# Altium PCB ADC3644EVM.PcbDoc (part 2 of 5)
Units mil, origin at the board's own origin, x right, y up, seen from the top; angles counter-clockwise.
Board outline 3900 x 2716.54 mil, 10 copper layers (Top Layer, L2 GND, L3 PWR, L4 GND, L5 SIG, L6 GND, L7 GND, L8 PWR, L9 GND, Bottom Layer), stack 61.2 mil thick; 368 components, 252 nets, 1539 pads, 1019 vias.
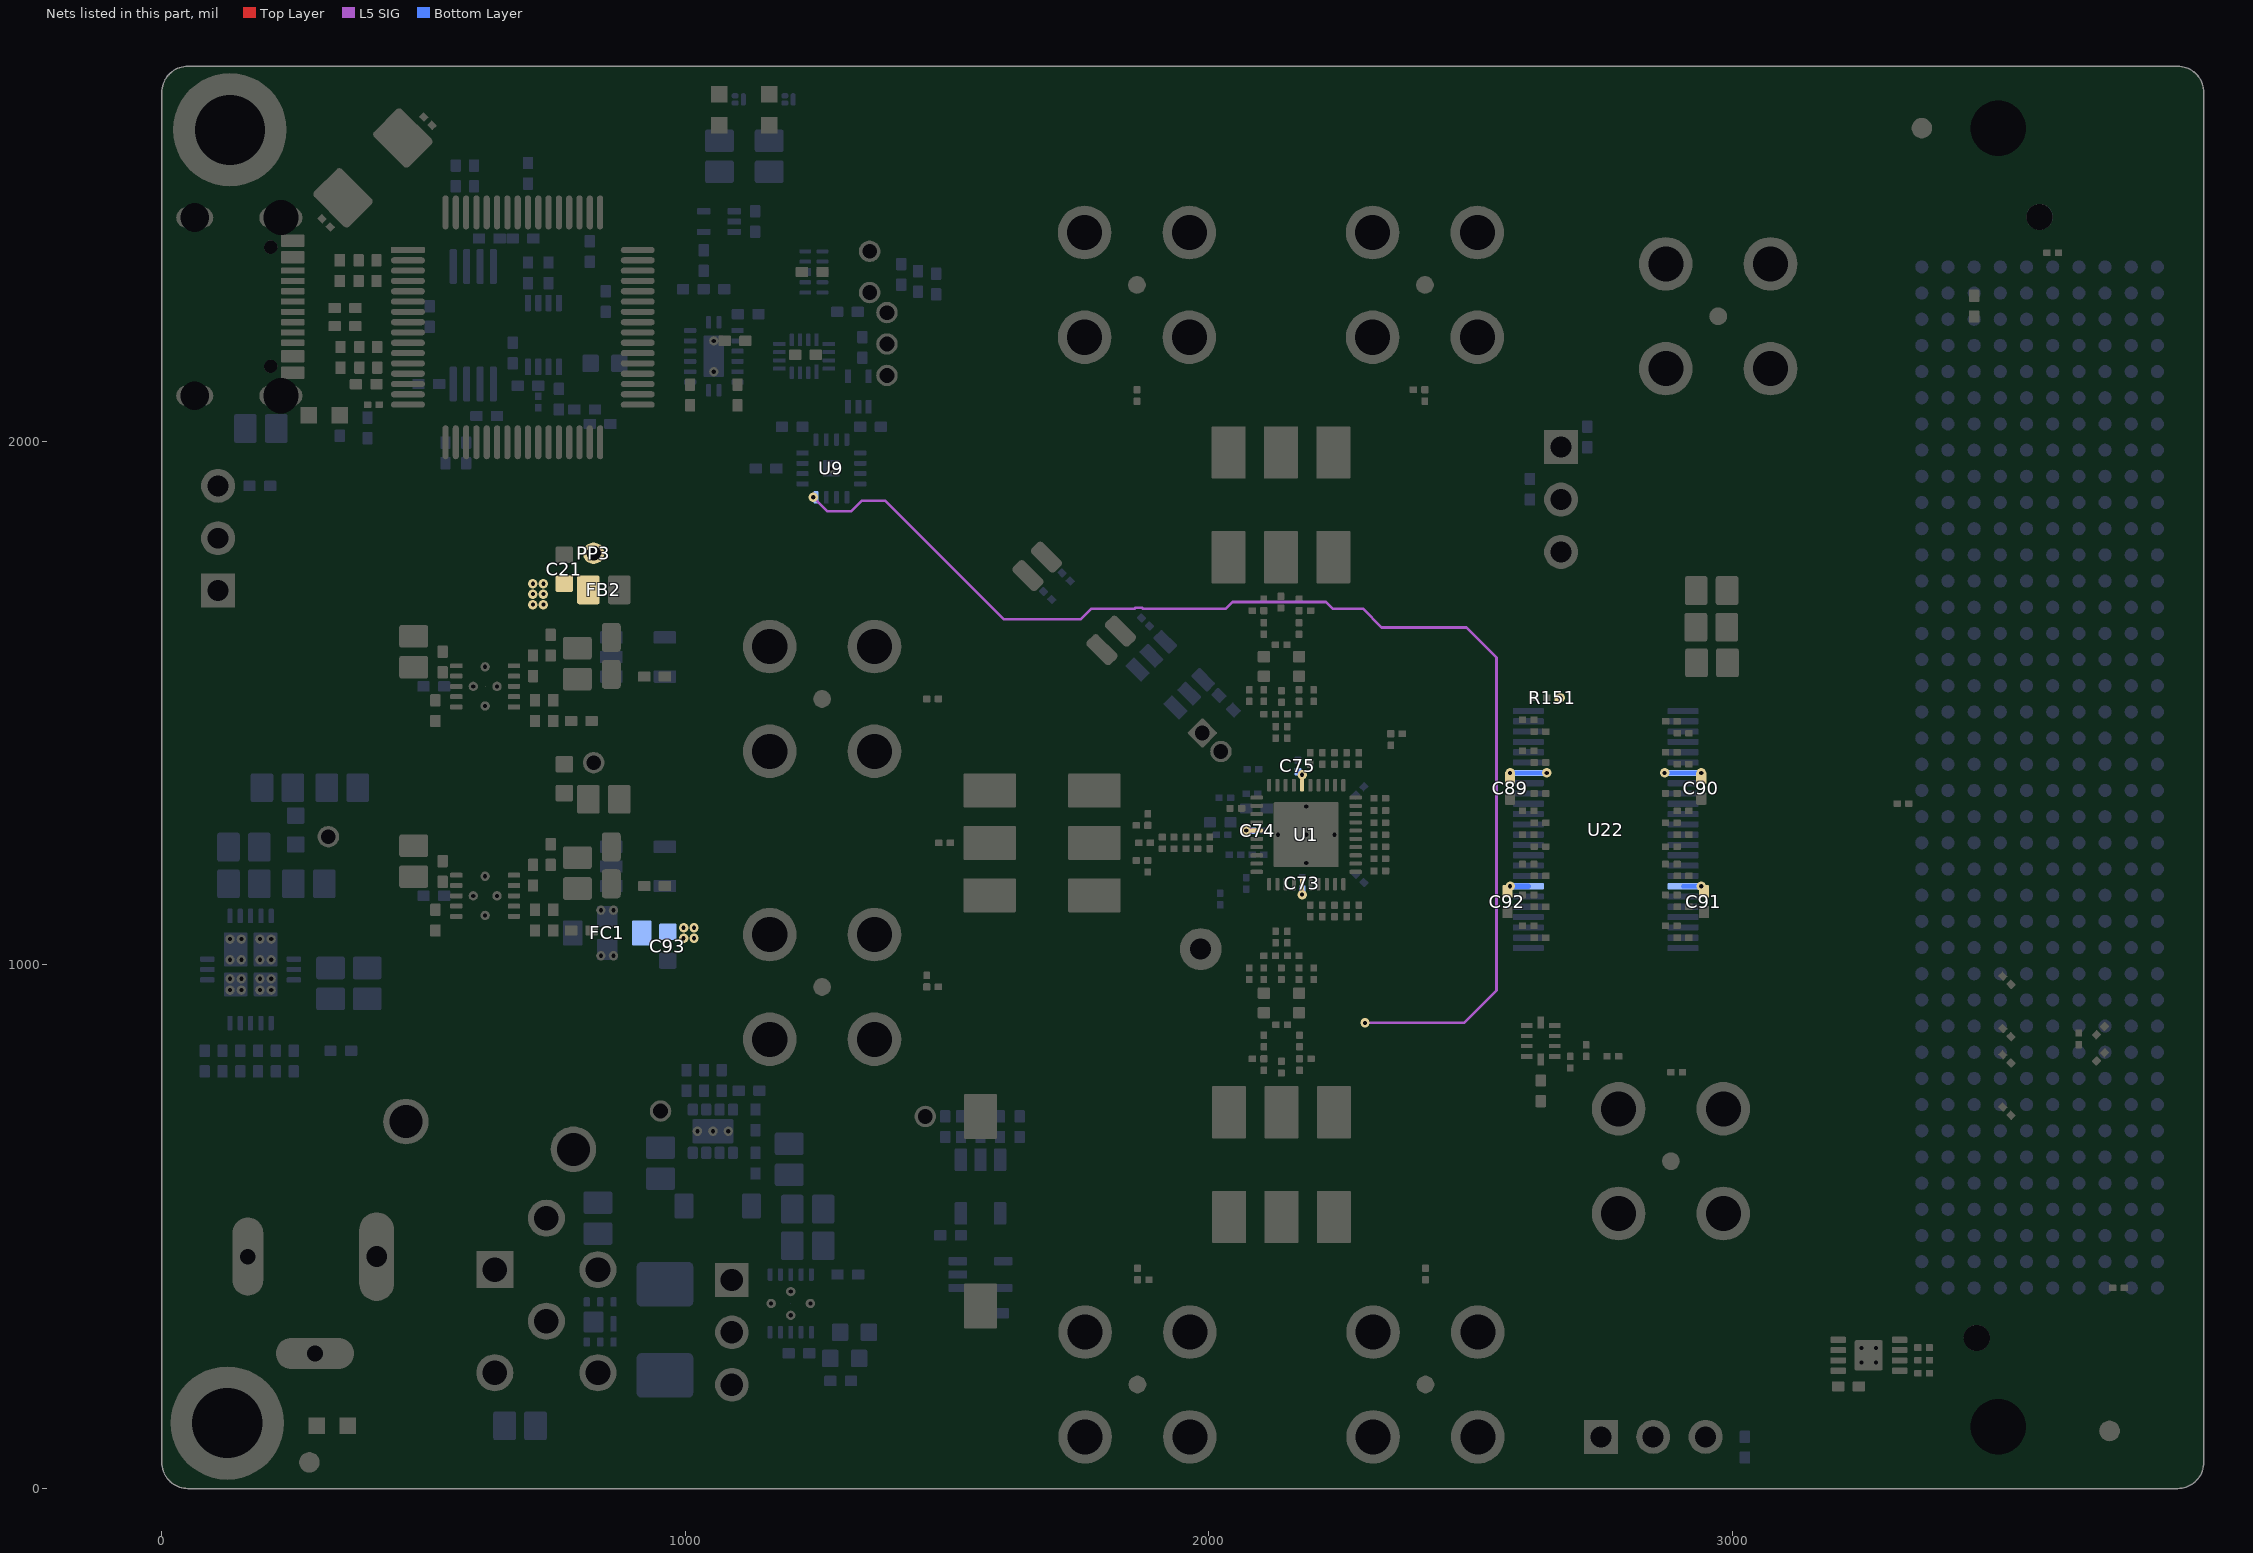
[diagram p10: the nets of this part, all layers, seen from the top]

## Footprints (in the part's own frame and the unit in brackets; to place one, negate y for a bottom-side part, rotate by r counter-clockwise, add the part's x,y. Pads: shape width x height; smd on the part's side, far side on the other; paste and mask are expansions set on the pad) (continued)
IND_LQG15H [mm] "MuRata"
  rrect20% 0.55x0.6 smd mask+0.07: 1(-0.475,0) 2(0.475,0)
  body extent -0.52,-0.27 0.52,0.27, height 0.55
Keystone5010 [mil] "Keystone Multipurpose loops"
  round 87 hole 63: 1(0,0)
  silkscreen extent -70,-70 70,70, body extent -63,-63 63,62, height 319
KEYSTONE5116 [mil] "For Keystone 500x miniature loop terminals"
  round 80 hole 40: 1(0,0)
  silkscreen extent -58,-58 58,58, body extent -50,-49 50,51, height 183
Keystone5125 [mil] "Keystone Multipurpose loops"
  round 87 hole 63: 1(0,0)
  silkscreen extent -70,-70 70,70, body extent -63,-63 63,62, height 319
Label_650x200 [mil] "Thermal Transfer Label"
  silkscreen extent -325,-100 325,100
LED_LTST-C190-Green [mm] "Lite-On"
  rect 0.8x0.8 smd: 1(-0.75,0) 2(0.75,0)
  silkscreen extent -1.1,-0.8 1.8,0.8, body extent -0.85,-0.45 0.85,0.45, height 0.91
LQFP64-MFG [mm]
  rrect33% 1.65x0.3 smd paste+0 mask+0.05: 1(-5.575,3.75)
  rrect100% 1.65x0.3 smd paste+0 mask+0.05: 2(-5.575,3.25) 3(-5.575,2.75) 4(-5.575,2.25) 5(-5.575,1.75) 6(-5.575,1.25) 7(-5.575,0.75) 8(-5.575,0.25) 9(-5.575,-0.25) 10(-5.575,-0.75) 11(-5.575,-1.25) 12(-5.575,-1.75) 13(-5.575,-2.25) 14(-5.575,-2.75) 15(-5.575,-3.25) 16(-5.575,-3.75) 33(5.575,-3.75) 34(5.575,-3.25) 35(5.575,-2.75) 36(5.575,-2.25) 37(5.575,-1.75) 38(5.575,-1.25) 39(5.575,-0.75) 40(5.575,-0.25) 41(5.575,0.25) 42(5.575,0.75) 43(5.575,1.25) 44(5.575,1.75) 45(5.575,2.25) 46(5.575,2.75) 47(5.575,3.25) 48(5.575,3.75)
  rrect100% 0.3x1.65 smd paste+0 mask+0.05: 17(-3.75,-5.575) 18(-3.25,-5.575) 19(-2.75,-5.575) 20(-2.25,-5.575) 21(-1.75,-5.575) 22(-1.25,-5.575) 23(-0.75,-5.575) 24(-0.25,-5.575) 25(0.25,-5.575) 26(0.75,-5.575) 27(1.25,-5.575) 28(1.75,-5.575) 29(2.25,-5.575) 30(2.75,-5.575) 31(3.25,-5.575) 32(3.75,-5.575) 49(3.75,5.575) 50(3.25,5.575) 51(2.75,5.575) 52(2.25,5.575) 53(1.75,5.575) 54(1.25,5.575) 55(0.75,5.575) 56(0.25,5.575) 57(-0.25,5.575) 58(-0.75,5.575) 59(-1.25,5.575) 60(-1.75,5.575) 61(-2.25,5.575) 62(-2.75,5.575) 63(-3.25,5.575) 64(-3.75,5.575)
  silkscreen extent -7.12,-5.05 5.05,5.05, body extent -6.5,-6.5 6.5,6.5, height 0.25
NFM31PC [mm]
  rrect10% 0.95x1.2 smd paste+0: 1(-1.675,0) 3(1.675,0)
  round 0.2 / inner round 0.454 / far side round 0.454 hole 0.2 mask+0.05: 2(-0.305,-1.105) 2(-0.305,1.105) 2(0.305,-1.105) 2(0.305,1.105)
  rrect10% 1x1 smd paste+0: 2(0,-0.8) 2(0,0.8)
  body extent -1.7,-0.9 1.7,0.9, height 1.5
PBC03SAAN [mm] "Sullins 100mil, 1x3, 230 mil above insulator"
  rect 1.65x1.65 hole 1.016: 1(-2.54,0)
  round 1.65 hole 1.016: 2(0,0) 3(2.54,0)
  silkscreen extent -3.81,-1.27 3.81,1.6, body extent -3.81,-1.27 3.81,1.27, height 8.38
ProbePoint_TH_40mil [mil]
  round 41 hole 28: 1(0,0)
RAPC722X [mm] "Conn_DC Jack"
  oval 1.7x4.3 hole 1.01 slot 3.56 at 90 deg: 1(14.194,0)
  oval 1.5x3.8 hole 0.76 slot 3.05 at 90 deg: 2(7.946,0)
  oval 3.8x1.5 hole 0.76 slot 3.05 at 0 deg: 3(11.197,-4.7)
  silkscreen extent 0.2,-4.57 14.93,4.57, body extent 0.58,-4.97 15.06,4.56, height 10.92
RDU0028A [mm]
  round 0.025 smd mask+0.05: 1(-1.987,2.487) 2(-2.1,1.25) 6(-2.1,-1.25) 7(-1.987,-2.488) 13(1.987,-2.488) 14(2.1,-1.25) 18(2.1,1.25) 19(1.988,2.488)
  rrect40% 0.7x0.25 smd paste+0 mask+0.05: 3(-2.1,0.5) 4(-2.1,0) 5(-2.1,-0.5) 15(2.1,-0.5) 16(2.1,0) 17(2.1,0.5)
  rrect40% 0.25x0.7 smd paste+0 mask+0.05: 8(-1,-2.6) 9(-0.5,-2.6) 10(0,-2.6) 11(0.5,-2.6) 12(1,-2.6) 20(1,2.6) 21(0.5,2.6) 22(0,2.6) 23(-0.5,2.6) 24(-1,2.6)
  round 0.454 hole 0.2 mask+0.102: 25(-1,1) 25(-1,0.45) 25(-0.45,1) 25(-0.45,0.45) 26(-1,-1.475) 26(-1,-0.475) 26(-0.45,-1.475) 26(-0.45,-0.475) 27(0.45,-1.475) 27(0.45,-0.475) 27(1,-1.475) 27(1,-0.475) 28(0.45,1) 28(0.45,0.45) 28(1,1) 28(1,0.45)
  rrect9% 1.15x1.15 smd paste-1000 mask+0.05: 25(-0.725,0.725) 28(0.725,0.725)
  rrect9% 1.15x1.65 smd paste-1000 mask+0.05: 26(-0.725,-0.975) 27(0.725,-0.975)
  Top Layer region: -2.4,1.625 -1.8,1.625 -1.781,1.621 -1.765,1.61 -1.754,1.594 -1.75,1.575 -1.75,1.575 -1.75,0.925 -1.754,0.906 -1.765,0.89 -1.781,0.879 -1.8,0.875 -1.8,0.875 -2.4,0.875 -2.419,0.879 -2.435,0.89 -2.446,0.906 -2.45,0.925 -2.45,0.925 -2.45,1.075 -2.443,1.1 -2.425,1.118 -2.4,1.125 -2.4,1.125 -2.225,1.125 -2.187,1.133 -2.154,1.154 -2.133,1.187 -2.125,1.225 -2.125,1.225 -2.125,1.275 -2.138,1.325 -2.175,1.362 -2.225,1.375 -2.225,1.375 -2.4,1.375 -2.419,1.379 -2.435,1.39 -2.446,1.406 -2.45,1.425 -2.45,1.425 -2.45,1.575 -2.443,1.6 -2.425,1.618 -2.4,1.625
  Top Layer region: -2.4,-0.875 -1.8,-0.875 -1.775,-0.882 -1.757,-0.9 -1.75,-0.925 -1.75,-0.925 -1.75,-1.575 -1.754,-1.594 -1.765,-1.61 -1.781,-1.621 -1.8,-1.625 -1.8,-1.625 -2.4,-1.625 -2.419,-1.621 -2.435,-1.61 -2.446,-1.594 -2.45,-1.575 -2.45,-1.575 -2.45,-1.425 -2.443,-1.4 -2.425,-1.382 -2.4,-1.375 -2.4,-1.375 -2.225,-1.375 -2.187,-1.367 -2.154,-1.346 -2.133,-1.313 -2.125,-1.275 -2.125,-1.275 -2.125,-1.225 -2.138,-1.175 -2.175,-1.138 -2.225,-1.125 -2.225,-1.125 -2.4,-1.125 -2.419,-1.121 -2.435,-1.11 -2.446,-1.094 -2.45,-1.075 -2.45,-1.075 -2.45,-0.925 -2.443,-0.9 -2.425,-0.882 -2.4,-0.875
  Top Layer region: -1.575,-2.95 -1.55,-2.943 -1.532,-2.925 -1.525,-2.9 -1.525,-2.9 -1.525,-2.075 -1.529,-2.056 -1.54,-2.04 -1.556,-2.029 -1.575,-2.025 -1.575,-2.025 -2.4,-2.025 -2.423,-2.033 -2.439,-2.051 -2.445,-2.075 -2.445,-2.075 -2.45,-2.225 -2.443,-2.25 -2.425,-2.268 -2.4,-2.275 -2.4,-2.275 -2.225,-2.275 -2.187,-2.283 -2.154,-2.304 -2.133,-2.337 -2.125,-2.375 -2.125,-2.375 -2.125,-2.575 -2.118,-2.6 -2.1,-2.618 -2.075,-2.625 -2.075,-2.625 -1.875,-2.625 -1.837,-2.633 -1.804,-2.654 -1.783,-2.687 -1.775,-2.725 -1.775,-2.725 -1.775,-2.9 -1.768,-2.925 -1.75,-2.943 -1.725,-2.95 -1.725,-2.95
  Top Layer region: 1.575,-2.95 1.55,-2.943 1.532,-2.925 1.525,-2.9 1.525,-2.9 1.525,-2.075 1.529,-2.056 1.54,-2.04 1.556,-2.029 1.575,-2.025 1.575,-2.025 2.4,-2.025 2.423,-2.033 2.439,-2.051 2.445,-2.075 2.445,-2.075 2.45,-2.225 2.443,-2.25 2.425,-2.268 2.4,-2.275 2.4,-2.275 2.225,-2.275 2.187,-2.283 2.154,-2.304 2.133,-2.337 2.125,-2.375 2.125,-2.375 2.125,-2.575 2.118,-2.6 2.1,-2.618 2.075,-2.625 2.075,-2.625 1.875,-2.625 1.837,-2.633 1.804,-2.654 1.783,-2.687 1.775,-2.725 1.775,-2.725 1.775,-2.9 1.768,-2.925 1.75,-2.943 1.725,-2.95 1.725,-2.95
  Top Layer region: 2.4,-1.625 1.8,-1.625 1.775,-1.618 1.757,-1.6 1.75,-1.575 1.75,-1.575 1.75,-0.925 1.754,-0.906 1.765,-0.89 1.781,-0.879 1.8,-0.875 1.8,-0.875 2.4,-0.875 2.419,-0.879 2.435,-0.89 2.446,-0.906 2.45,-0.925 2.45,-0.925 2.45,-1.075 2.443,-1.1 2.425,-1.118 2.4,-1.125 2.4,-1.125 2.225,-1.125 2.187,-1.133 2.154,-1.154 2.133,-1.187 2.125,-1.225 2.125,-1.225 2.125,-1.275 2.138,-1.325 2.175,-1.362 2.225,-1.375 2.225,-1.375 2.4,-1.375 2.419,-1.379 2.435,-1.39 2.446,-1.406 2.45,-1.425 2.45,-1.425 2.45,-1.575 2.443,-1.6 2.425,-1.618 2.4,-1.625
  Top Layer region: 2.4,0.875 1.8,0.875 1.775,0.882 1.757,0.9 1.75,0.925 1.75,0.925 1.75,1.575 1.754,1.594 1.765,1.61 1.781,1.621 1.8,1.625 1.8,1.625 2.4,1.625 2.419,1.621 2.435,1.61 2.446,1.594 2.45,1.575 2.45,1.575 2.45,1.425 2.443,1.4 2.425,1.382 2.4,1.375 2.4,1.375 2.225,1.375 2.187,1.367 2.154,1.346 2.133,1.313 2.125,1.275 2.125,1.275 2.125,1.225 2.138,1.175 2.175,1.138 2.225,1.125 2.225,1.125 2.4,1.125 2.419,1.121 2.435,1.11 2.446,1.094 2.45,1.075 2.45,1.075 2.45,0.925 2.443,0.9 2.425,0.882 2.4,0.875
  Top Layer region: 1.575,2.95 1.55,2.943 1.532,2.925 1.525,2.9 1.525,2.9 1.525,2.075 1.529,2.056 1.54,2.04 1.556,2.029 1.575,2.025 1.575,2.025 2.4,2.025 2.423,2.033 2.439,2.051 2.445,2.075 2.445,2.075 2.45,2.225 2.443,2.25 2.425,2.268 2.4,2.275 2.4,2.275 2.225,2.275 2.187,2.283 2.154,2.304 2.133,2.337 2.125,2.375 2.125,2.375 2.125,2.575 2.118,2.6 2.1,2.618 2.075,2.625 2.075,2.625 1.875,2.625 1.837,2.633 1.804,2.654 1.783,2.687 1.775,2.725 1.775,2.725 1.775,2.9 1.768,2.925 1.75,2.943 1.725,2.95 1.725,2.95
  Top Layer region: -1.575,2.95 -1.55,2.943 -1.532,2.925 -1.525,2.9 -1.525,2.9 -1.525,2.075 -1.529,2.056 -1.54,2.04 -1.556,2.029 -1.575,2.025 -1.575,2.025 -2.4,2.025 -2.423,2.033 -2.439,2.051 -2.445,2.075 -2.445,2.075 -2.45,2.225 -2.443,2.25 -2.425,2.268 -2.4,2.275 -2.4,2.275 -2.225,2.275 -2.187,2.283 -2.154,2.304 -2.133,2.337 -2.125,2.375 -2.125,2.375 -2.125,2.575 -2.118,2.6 -2.1,2.618 -2.075,2.625 -2.075,2.625 -1.875,2.625 -1.837,2.633 -1.804,2.654 -1.783,2.687 -1.775,2.725 -1.775,2.725 -1.775,2.9 -1.768,2.925 -1.75,2.943 -1.725,2.95 -1.725,2.95
  silkscreen extent -3.2,-3.13 2.63,3.13, body extent -2.25,-2.75 2.25,2.75, height 1.9
RSB0040E [mm] "WQFN-40"
  rrect50% 0.6x0.2 smd mask+0.05: 1(-2.4,1.8) 2(-2.4,1.4) 3(-2.4,1) 4(-2.4,0.6) 5(-2.4,0.2) 6(-2.4,-0.2) 7(-2.4,-0.6) 8(-2.4,-1) 9(-2.4,-1.4) 10(-2.4,-1.8) 21(2.4,-1.8) 22(2.4,-1.4) 23(2.4,-1) 24(2.4,-0.6) 25(2.4,-0.2) 26(2.4,0.2) 27(2.4,0.6) 28(2.4,1) 29(2.4,1.4) 30(2.4,1.8)
  rrect50% 0.2x0.6 smd mask+0.05: 11(-1.8,-2.4) 12(-1.4,-2.4) 13(-1,-2.4) 14(-0.6,-2.4) 15(-0.2,-2.4) 16(0.2,-2.4) 17(0.6,-2.4) 18(1,-2.4) 19(1.4,-2.4) 20(1.8,-2.4) 31(1.8,2.4) 32(1.4,2.4) 33(1,2.4) 34(0.6,2.4) 35(0.2,2.4) 36(-0.2,2.4) 37(-0.6,2.4) 38(-1,2.4) 39(-1.4,2.4) 40(-1.8,2.4)
  round 0.2 / inner round 0.454 / far side round 0.454 hole 0.2 mask+0.05: 41(-1.37,0) 41(0,-1.37) 41(0,0) 41(0,1.37) 41(1.37,0)
  rrect3% 3.15x3.15 smd paste-1.75 mask+0.05: 41(0,0)
  silkscreen extent -2.86,2.27 -2.8,2.33, body extent -2.5,-2.5 2.5,2.5, height 0.8
RSE0010A [mm] "QFN, 10-Leads, Body 1.5x2mm, Pitch 0.5mm, TI Recommended"
  rrect20% 0.55x0.25 smd mask+0.07: 1(-0.675,0.75) 4(-0.675,-0.75) 6(0.675,-0.75) 9(0.675,0.75)
  rrect20% 0.55x0.2 smd mask+0.07: 2(-0.675,0.25) 3(-0.675,-0.25) 7(0.675,-0.25) 8(0.675,0.25)
  rrect20% 0.3x0.6 smd mask+0.07: 5(0,-0.9) 10(0,0.9)
  silkscreen extent -1.07,-1.17 0.77,1.18, body extent -0.75,-1 0.75,1, height 0.54
RSV0016A [mm] "QFN, 16-Leads, Body 1.8x2.6mm, Pitch 0.4mm, TI Recommended"
  rrect25% 0.7x0.2 smd mask+0.05: 1(-0.75,0.6)
  rrect25% 0.6x0.2 smd mask+0.05: 2(-0.8,0.2) 3(-0.8,-0.2) 4(-0.8,-0.6) 9(0.8,-0.6) 10(0.8,-0.2) 11(0.8,0.2) 12(0.8,0.6)
  rrect25% 0.2x0.6 smd mask+0.05: 5(-0.6,-1.2) 6(-0.2,-1.2) 7(0.2,-1.2) 8(0.6,-1.2) 13(0.6,1.2) 14(0.2,1.2) 15(-0.2,1.2) 16(-0.6,1.2)
  silkscreen extent -1.08,-1.33 1.08,1.45, body extent -0.85,-1.31 0.85,1.31, height 0.49
RTE0016D [mm]
  rrect42% 0.6x0.24 smd paste+0 mask+0.07: 1(-1.4,0.75) 2(-1.4,0.25) 3(-1.4,-0.25) 4(-1.4,-0.75) 9(1.4,-0.75) 10(1.4,-0.25) 11(1.4,0.25) 12(1.4,0.75)
  rrect42% 0.24x0.6 smd paste+0 mask+0.07: 5(-0.75,-1.4) 6(-0.25,-1.4) 7(0.25,-1.4) 8(0.75,-1.4) 13(0.75,1.4) 14(0.25,1.4) 15(-0.25,1.4) 16(-0.75,1.4)
  round 0.454 hole 0.2 mask+0.05: 17(0,0)
  rrect6% 0.8x0.8 smd paste-0.04 mask+0: 17(0,0)
  silkscreen extent -2.06,-1.55 1.55,1.55, body extent -1.5,-1.5 1.5,1.5, height 0.8
SAMTEC_ASP-134488-01 [mm]
  round 0.64 smd paste+0.125: A1(24.74,5.715) A2(23.47,5.715) A3(22.2,5.715) A4(20.93,5.715) A5(19.66,5.715) A6(18.39,5.715) A7(17.12,5.715) A8(15.85,5.715) A9(14.58,5.715) A10(13.31,5.715) A11(12.04,5.715) A12(10.77,5.715) A13(9.5,5.715) A14(8.23,5.715) A15(6.96,5.715) A16(5.69,5.715) A17(4.42,5.715) A18(3.15,5.715) A19(1.88,5.715) A20(0.61,5.715) A21(-0.66,5.715) A22(-1.93,5.715) A23(-3.2,5.715) A24(-4.47,5.715) A25(-5.74,5.715) A26(-7.01,5.715) A27(-8.28,5.715) A28(-9.55,5.715) A29(-10.82,5.715) A30(-12.09,5.715) A31(-13.36,5.715) A32(-14.63,5.715) A33(-15.9,5.715) A34(-17.17,5.715) A35(-18.44,5.715) A36(-19.71,5.715) A37(-20.98,5.715) A38(-22.25,5.715) A39(-23.52,5.715) A40(-24.79,5.715) B1(24.74,4.445) B2(23.47,4.445) B3(22.2,4.445) B4(20.93,4.445) B5(19.66,4.445) B6(18.39,4.445) B7(17.12,4.445) B8(15.85,4.445) B9(14.58,4.445) B10(13.31,4.445) B11(12.04,4.445) B12(10.77,4.445) B13(9.5,4.445) B14(8.23,4.445) B15(6.96,4.445) B16(5.69,4.445) B17(4.42,4.445) B18(3.15,4.445) B19(1.88,4.445) B20(0.61,4.445) B21(-0.66,4.445) B22(-1.93,4.445) B23(-3.2,4.445) B24(-4.47,4.445) B25(-5.74,4.445) B26(-7.01,4.445) B27(-8.28,4.445) B28(-9.55,4.445) B29(-10.82,4.445) B30(-12.09,4.445) B31(-13.36,4.445) B32(-14.63,4.445) B33(-15.9,4.445) B34(-17.17,4.445) B35(-18.44,4.445) B36(-19.71,4.445) B37(-20.98,4.445) B38(-22.25,4.445) B39(-23.52,4.445) B40(-24.79,4.445) C1(24.74,3.175) C2(23.47,3.175) C3(22.2,3.175) C4(20.93,3.175) C5(19.66,3.175) C6(18.39,3.175) C7(17.12,3.175) C8(15.85,3.175) C9(14.58,3.175) C10(13.31,3.175) C11(12.04,3.175) C12(10.77,3.175) C13(9.5,3.175) C14(8.23,3.175) C15(6.96,3.175) C16(5.69,3.175) C17(4.42,3.175) C18(3.15,3.175) C19(1.88,3.175) C20(0.61,3.175) C21(-0.66,3.175) C22(-1.93,3.175) C23(-3.2,3.175) C24(-4.47,3.175) C25(-5.74,3.175) C26(-7.01,3.175) C27(-8.28,3.175) C28(-9.55,3.175) C29(-10.82,3.175) C30(-12.09,3.175) C31(-13.36,3.175) C32(-14.63,3.175) C33(-15.9,3.175) C34(-17.17,3.175) C35(-18.44,3.175) C36(-19.71,3.175) C37(-20.98,3.175) C38(-22.25,3.175) C39(-23.52,3.175) C40(-24.79,3.175) D1(24.74,1.905) D2(23.47,1.905) D3(22.2,1.905) D4(20.93,1.905) D5(19.66,1.905) D6(18.39,1.905) D7(17.12,1.905) D8(15.85,1.905) D9(14.58,1.905) D10(13.31,1.905) D11(12.04,1.905) D12(10.77,1.905) D13(9.5,1.905) D14(8.23,1.905) D15(6.96,1.905) D16(5.69,1.905) D17(4.42,1.905) D18(3.15,1.905) D19(1.88,1.905) D20(0.61,1.905) D21(-0.66,1.905) D22(-1.93,1.905) D23(-3.2,1.905) D24(-4.47,1.905) D25(-5.74,1.905) D26(-7.01,1.905) D27(-8.28,1.905) D28(-9.55,1.905) D29(-10.82,1.905) D30(-12.09,1.905) D31(-13.36,1.905) D32(-14.63,1.905) D33(-15.9,1.905) D34(-17.17,1.905) D35(-18.44,1.905) D36(-19.71,1.905) D37(-20.98,1.905) D38(-22.25,1.905) D39(-23.52,1.905) D40(-24.79,1.905) E1(24.74,0.635) E2(23.47,0.635) E3(22.2,0.635) E4(20.93,0.635) E5(19.66,0.635) E6(18.39,0.635) E7(17.12,0.635) E8(15.85,0.635) E9(14.58,0.635) E10(13.31,0.635) E11(12.04,0.635) E12(10.77,0.635) E13(9.5,0.635) E14(8.23,0.635) E15(6.96,0.635) E16(5.69,0.635) E17(4.42,0.635) E18(3.15,0.635) E19(1.88,0.635) E20(0.61,0.635) E21(-0.66,0.635) E22(-1.93,0.635) E23(-3.2,0.635) E24(-4.47,0.635) E25(-5.74,0.635) E26(-7.01,0.635) E27(-8.28,0.635) E28(-9.55,0.635) E29(-10.82,0.635) E30(-12.09,0.635) E31(-13.36,0.635) E32(-14.63,0.635) E33(-15.9,0.635) E34(-17.17,0.635) E35(-18.44,0.635) E36(-19.71,0.635) E37(-20.98,0.635) E38(-22.25,0.635) E39(-23.52,0.635) E40(-24.79,0.635) F1(24.74,-0.635) F2(23.47,-0.635) F3(22.2,-0.635) F4(20.93,-0.635) F5(19.66,-0.635) F6(18.39,-0.635) F7(17.12,-0.635) F8(15.85,-0.635) F9(14.58,-0.635) F10(13.31,-0.635) F11(12.04,-0.635) F12(10.77,-0.635) F13(9.5,-0.635) F14(8.23,-0.635) F15(6.96,-0.635) F16(5.69,-0.635) F17(4.42,-0.635) F18(3.15,-0.635) F19(1.88,-0.635) F20(0.61,-0.635) F21(-0.66,-0.635) F22(-1.93,-0.635) F23(-3.2,-0.635) F24(-4.47,-0.635) F25(-5.74,-0.635) F26(-7.01,-0.635) F27(-8.28,-0.635) F28(-9.55,-0.635) F29(-10.82,-0.635) F30(-12.09,-0.635) F31(-13.36,-0.635) F32(-14.63,-0.635) F33(-15.9,-0.635) F34(-17.17,-0.635) F35(-18.44,-0.635) F36(-19.71,-0.635) F37(-20.98,-0.635) F38(-22.25,-0.635) F39(-23.52,-0.635) F40(-24.79,-0.635) G1(24.74,-1.905) G2(23.47,-1.905) G3(22.2,-1.905) G4(20.93,-1.905) G5(19.66,-1.905) G6(18.39,-1.905) G7(17.12,-1.905) G8(15.85,-1.905) G9(14.58,-1.905) G10(13.31,-1.905) G11(12.04,-1.905) G12(10.77,-1.905) G13(9.5,-1.905) G14(8.23,-1.905) G15(6.96,-1.905) G16(5.69,-1.905) G17(4.42,-1.905) G18(3.15,-1.905) G19(1.88,-1.905) G20(0.61,-1.905) G21(-0.66,-1.905) G22(-1.93,-1.905) G23(-3.2,-1.905) G24(-4.47,-1.905) G25(-5.74,-1.905) G26(-7.01,-1.905) G27(-8.28,-1.905) G28(-9.55,-1.905) G29(-10.82,-1.905) G30(-12.09,-1.905) G31(-13.36,-1.905) G32(-14.63,-1.905) G33(-15.9,-1.905) G34(-17.17,-1.905) G35(-18.44,-1.905) G36(-19.71,-1.905) G37(-20.98,-1.905) G38(-22.25,-1.905) G39(-23.52,-1.905) G40(-24.79,-1.905) H1(24.74,-3.175) H2(23.47,-3.175) H3(22.2,-3.175) H4(20.93,-3.175) H5(19.66,-3.175) H6(18.39,-3.175) H7(17.12,-3.175) H8(15.85,-3.175) H9(14.58,-3.175) H10(13.31,-3.175) H11(12.04,-3.175) H12(10.77,-3.175) H13(9.5,-3.175) H14(8.23,-3.175) H15(6.96,-3.175) H16(5.69,-3.175) H17(4.42,-3.175) H18(3.15,-3.175) H19(1.88,-3.175) H20(0.61,-3.175) H21(-0.66,-3.175) H22(-1.93,-3.175) H23(-3.2,-3.175) H24(-4.47,-3.175) H25(-5.74,-3.175) H26(-7.01,-3.175) H27(-8.28,-3.175) H28(-9.55,-3.175) H29(-10.82,-3.175) H30(-12.09,-3.175) H31(-13.36,-3.175) H32(-14.63,-3.175) H33(-15.9,-3.175) H34(-17.17,-3.175) H35(-18.44,-3.175) H36(-19.71,-3.175) H37(-20.98,-3.175) H38(-22.25,-3.175) H39(-23.52,-3.175) H40(-24.79,-3.175) J1(24.74,-4.445) J2(23.47,-4.445) J3(22.2,-4.445) J4(20.93,-4.445) J5(19.66,-4.445) J6(18.39,-4.445) J7(17.12,-4.445) J8(15.85,-4.445) J9(14.58,-4.445) J10(13.31,-4.445) J11(12.04,-4.445) J12(10.77,-4.445) J13(9.5,-4.445) J14(8.23,-4.445) J15(6.96,-4.445) J16(5.69,-4.445) J17(4.42,-4.445) J18(3.15,-4.445) J19(1.88,-4.445) J20(0.61,-4.445) J21(-0.66,-4.445) J22(-1.93,-4.445) J23(-3.2,-4.445) J24(-4.47,-4.445) J25(-5.74,-4.445) J26(-7.01,-4.445) J27(-8.28,-4.445) J28(-9.55,-4.445) J29(-10.82,-4.445) J30(-12.09,-4.445) J31(-13.36,-4.445) J32(-14.63,-4.445) J33(-15.9,-4.445) J34(-17.17,-4.445) J35(-18.44,-4.445) J36(-19.71,-4.445) J37(-20.98,-4.445) J38(-22.25,-4.445) J39(-23.52,-4.445) J40(-24.79,-4.445) K1(24.74,-5.715) K2(23.47,-5.715) K3(22.2,-5.715) K4(20.93,-5.715) K5(19.66,-5.715) K6(18.39,-5.715) K7(17.12,-5.715) K8(15.85,-5.715) K9(14.58,-5.715) K10(13.31,-5.715) K11(12.04,-5.715) K12(10.77,-5.715) K13(9.5,-5.715) K14(8.23,-5.715) K15(6.96,-5.715) K16(5.69,-5.715) K17(4.42,-5.715) K18(3.15,-5.715) K19(1.88,-5.715) K20(0.61,-5.715) K21(-0.66,-5.715) K22(-1.93,-5.715) K23(-3.2,-5.715) K24(-4.47,-5.715) K25(-5.74,-5.715) K26(-7.01,-5.715) K27(-8.28,-5.715) K28(-9.55,-5.715) K29(-10.82,-5.715) K30(-12.09,-5.715) K31(-13.36,-5.715) K32(-14.63,-5.715) K33(-15.9,-5.715) K34(-17.17,-5.715) K35(-18.44,-5.715) K36(-19.71,-5.715) K37(-20.98,-5.715) K38(-22.25,-5.715) K39(-23.52,-5.715) K40(-24.79,-5.715)
  round 0 hole 2.69 unplated: ""(-31.521,-2.007) ""(31.471,-2.007)
  round 1.27 hole 1.27 unplated: ""(-27.216,-3.05) ""(27.166,0)
  silkscreen extent -27.92,-7.34 28.75,7.76, body extent -27.91,-7.34 28.76,7.34, height 7.11
SIL0008D [mm] "SIP, 8-Leads, Body 2.8x3.0mm, Pitch 0.65mm, Thermal Pad 1.9x1.1mm"
  rrect12% 1.04x0.85 on Bottom Paste: 0(0,-0.525) 0(0,0.525)
  rrect40% 0.6x0.5 smd paste-0.05 mask-0.05: 1(-1.05,0.975) 2(-1.05,0.325) 3(-1.05,-0.325) 4(-1.05,-0.975) 5(1.05,-0.975) 6(1.05,-0.325) 7(1.05,0.325) 8(1.05,0.975)
  round 0.457 hole 0.203 mask+0.05: 9(0,-0.75) 9(0,0) 9(0,0.75)
  rrect17% 1.2x2 smd paste-0.6 mask-0.05: 9(0,0)
  silkscreen extent -1.53,-1.63 1.53,1.63, body extent -1.4,-1.5 1.4,1.5, height 1.53
SMBJ15CA [mil]
  rrect20% 85x107.99 smd: 1(-87.01,0) 2(87.01,0)
  silkscreen extent -125,-79 125,79, body extent -104,-73 104,73, height 89
SOD-123 [mm] "On Semi recommended land pattern"
  rrect20% 0.915x1.22 smd: 1(-1.637,0) 2(1.637,0)
  silkscreen extent -2.74,-1.17 2.03,1.17, body extent -1.93,-0.9 1.93,0.9, height 1.35
SPC02SYAN [mil] "SULLINS"
  round 1 on Mech3: 0(0,0)
  body extent -98,-47 99,47, height 366
TDFN8 [mm]
  rrect30% 0.75x0.3 smd paste+0 mask+0.05: 1(-1.5,0.75) 2(-1.5,0.25) 3(-1.5,-0.25) 4(-1.5,-0.75) 5(1.478,-0.75) 6(1.478,-0.25) 7(1.478,0.25) 8(1.478,0.75)
  round 0.327 / inner round 0.454 / far side round 0.454 hole 0.2 mask+0.05: 9(-0.354,0.354) 9(-0.354,-0.354) 9(0.354,0.354) 9(0.354,-0.354)
  rrect10% 1.36x1.46 smd paste+0 mask+0.05: 9(0,0)
  silkscreen extent -1.56,1.07 -1.4,1.22, body extent -1.5,-1 1.5,1, height 0.75
TI_Stacked_Overlay_Small_Vertical [mil]
  silkscreen extent -66,-288 69,288
TSSOP-8 [mm] "TSSOP, 8-Leads, Body 3.1x4.5mm (max), Pitch 0.65mm, IPC Medium Density"
  rrect50% 1.7x0.35 smd: 1(-2.85,0.975) 2(-2.85,0.325) 3(-2.85,-0.325) 4(-2.85,-0.975) 5(2.85,-0.975) 6(2.85,-0.325) 7(2.85,0.325) 8(2.85,0.975)
  silkscreen extent -2.97,-1.55 1.6,1.82, body extent -3.2,-1.55 3.2,1.55, height 1.07
WEEE_Minimum [mil] "WEEElie bin"
  silkscreen extent -95,-172 99,104
XTAL_ABM3 [mm] "Abracon recommended land pattern 12.28.10"
  rrect20% 1.9x2.4 smd: 1(-2.05,0) 2(2.05,0)
  silkscreen extent -2.67,-1.78 2.67,1.78, body extent -2.6,-1.7 2.6,1.7, height 1.3
YJM0003A [mm] "SMT, 3-Leads, Body 0.69x0.6mm"
  rrect80% 0.35x0.25 smd paste-0.2 mask-0.05: 1(-0.175,0.175) 2(-0.175,-0.175)
  rrect50% 0.25x0.2 on Bottom Paste: 1(-0.175,0.2) 2(-0.175,-0.2)
  rrect80% 0.25x0.6 smd paste-0.05 mask-0.05: 3(0.225,0)
  body extent -0.35,-0.3 0.35,0.3, height 0.35

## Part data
C1 C2 C3: library part capcc02687, "CAP CER 1UF 50V X7R 0805", Manufacturer="TDK Corporation", Operating Temperature="-55°C ~ 125°C", Ratings=-, Supplier Part Number 1=445-7547-1-ND, Temperature Coefficient=X7R, Tolerance=±10%, Voltage - Rated=50V
C4 C5: library part capcc03751, "CAP CER 1000PF 50V X7R 0603", Manufacturer="TDK Corporation", Operating Temperature="-55°C ~ 125°C", Ratings=AEC-Q200, Supplier Part Number 1=445-5659-1-ND, Temperature Coefficient=X7R, Tolerance=±10%, Voltage - Rated=50V
C6 C9 C10 C18 C20 C24 C26: library part capcc03511, "CAP CER 10UF 25V X7S 0805", Manufacturer="TDK Corporation", Operating Temperature="-55°C ~ 125°C", Ratings=-, Supplier Part Number 1=445-181600-1-ND, Temperature Coefficient=X7S, Tolerance=±10%, Voltage - Rated=25V
C7 C11 C12 C13 C14 C15: library part capcc09395, "CAP CER 22UF 10V X7S 0805", Manufacturer="TDK Corporation", Operating Temperature="-55°C ~ 125°C", Ratings=-, Supplier Part Number 1=445-14560-1-ND, Temperature Coefficient=X7S, Tolerance=±20%, Voltage - Rated=10V
C8: library part capcc04738, "CAP CER 3300PF 50V X7R 0402", Manufacturer="TDK Corporation", Operating Temperature="-55°C ~ 125°C", Ratings=AEC-Q200, Supplier Part Number 1=445-6891-1-ND, Temperature Coefficient=X7R, Tolerance=±10%, Voltage - Rated=50V
C16: library part capcc01693, "CAP CER 0.22UF 16V X5R 0402", Manufacturer="TDK Corporation", Operating Temperature="-55°C ~ 85°C", Ratings=AEC-Q200, Supplier Part Number 1=445-12172-1-ND, Temperature Coefficient=X5R, Tolerance=±20%, Voltage - Rated=16V
C17 C19 C23 C25 C29 C30 C32 C34 C36 C37 C38 C39 C40 C41 C44 C45 C46 C47 C55 C80 C81 C85 C88 C89 C90 C91 C92: library part capcc09401, "CAP CER 0.1UF 25V X7R 0402", Manufacturer=Murata, Operating Temperature="-55°C ~ 125°C", Ratings=-, Supplier Part Number 1=490-GRT155R71E104KE01JCT-ND, Temperature Coefficient=X7R, Tolerance=±10%, Voltage - Rated=25V
C21 C27: "CAP CER 47UF 6.3V X5R 0603", Manufacturer=Murata, Operating Temperature="-55°C ~ 85°C", Ratings=-, Supplier Part Number 1=490-13247-1-ND, Temperature Coefficient=X5R, Tolerance=±20%, Voltage - Rated=6.3V
C22 C28: library part capcc02750, "CAP CER 1UF 25V X5R 0402", Manufacturer="TDK Corporation", Operating Temperature="-55°C ~ 85°C", Ratings=-, Supplier Part Number 1=445-9066-1-ND, Temperature Coefficient=X5R, Tolerance=±10%, Voltage - Rated=25V
C31 C33: library part capcc03298, "CAP CER 4.7UF 10V X5R 0402", Manufacturer="TDK Corporation", Operating Temperature="-55°C ~ 85°C", Ratings=-, Supplier Part Number 1=445-13820-1-ND, Temperature Coefficient=X5R, Tolerance=±10%, Voltage - Rated=10V
C35: library part capcc03130, "CAP CER 3.3UF 10V X5R 0603", Manufacturer="TDK Corporation", Operating Temperature="-55°C ~ 85°C", Ratings=AEC-Q200, Supplier Part Number 1=445-7879-1-ND, Temperature Coefficient=X5R, Tolerance=±10%, Voltage - Rated=10V
C42 C43: library part capcc08580, "CAP CER 18PF 25V C0H 0201", Manufacturer="Murata Electronics", Operating Temperature="-55°C ~ 125°C", Ratings=-, Temperature Coefficient=C0H, Tolerance=±5%, Voltage - Rated=25V
C48 C49 C50 C51 C52 C53 C54 C56 C57 C58 C59 C60 C61 C63 C64 C65 C66 C67 C68 C69 C71 C72 C74 C75 C77 C79 C83 C84 C87: library part capcc09270, "CAP CER 0.1UF 16V X7R 0201", Manufacturer="Murata Electronics", Operating Temperature="-55°C ~ 125°C", Ratings=-, Supplier Part Number 1=490-GRM033Z71C104ME14DCT-ND, Temperature Coefficient=X7R, Tolerance=±20%, Voltage - Rated=16V
C62 C70: library part capcc06388, "CAP CER 100PF 25V X7R 0201", Manufacturer="TDK Corporation", Operating Temperature="-55°C ~ 125°C", Ratings=AEC-Q200, Supplier Part Number 1=445-12088-1-ND, Temperature Coefficient=X7R, Tolerance=±20%, Voltage - Rated=25V
C73 C76 C78: library part capcc09264, "CAP CER 1UF 10V X5R 0201", Manufacturer="Murata Electronics", Operating Temperature="-55°C ~ 85°C", Ratings=-, Supplier Part Number 1=490-GRM033R61A105ME44DCT-ND, Temperature Coefficient=X5R, Tolerance=±20%, Voltage - Rated=10V
C82 C86: library part capcc09406, "CAP CER 10UF 10V X5R 0402", Manufacturer="KYOCERA AVX", Operating Temperature="-55°C ~ 85°C", Ratings=-, Supplier Part Number 1=478-10052-1-ND, Temperature Coefficient=X5R, Tolerance=±20%, Voltage - Rated=10V
C93: library part capcc09400, "CAP CER 10UF 25V X5R 0603", Manufacturer=Murata, Operating Temperature="-55°C ~ 85°C", Ratings=-, Supplier Part Number 1=490-GRM188R61E106KA73JCT-ND, Temperature Coefficient=X5R, Tolerance=±10%, Voltage - Rated=25V
D1 D4 D5 D6: library part cmp00247, "LED GREEN CLEAR CHIP SMD", Alt Manufacturer=-, Color=Green, Current Rating (Amps)=20mA, Manufacturer="Lite-On Inc.", Supplier Part Number 1=160-1888-1-ND, Voltage - Forward (Vf) (Typ)=3.2V
D2: library part cmp00440, "24.4V Clamp 24.6A Ipp Tvs Diode", Alt Manufacturer=-, Manufacturer=Littlefuse, Supplier Part Number 1=SMBJ15CALFCT-ND
D3: library part cmp00438, "DIODE SCHOTTKY 30V 1A SOD123", Alt Manufacturer="Rohm Semiconductor", Alt PartNumber=RB160M-30TR, Color=-, Manufacturer=Onsemi, Supplier Part Number 1=MBR130T1GOSCT-ND
F1: library part cmp00325, "EMI Filter Circuits 40 DB 50V 10A", Alt Manufacturer=-, Manufacturer="Murata Electronics", Supplier Part Number 1=81-BNX002-11
FB1: library part dcp00004, "8.5 Ohms @ 100 MHz 1 Power Line Ferrite Bead 0603 (1608 Metric) 8A 4mOhm", Current=8A, Manufacturer=Murata, Operating Temperature="-55°C ~ 125°C", Supplier Part Number 1=490-BLE18PS080SN1DCT-ND, Temperature Coefficient=-
FB2 FB3: library part dcp00579, "FERRITEBEAD SMD Z100MHZ=470OHM 2", Current=2.5A, Manufacturer="Murata Electronics", Operating Temperature="-55°C ~ 125°C", Supplier Part Number 1=490-18594-1-ND, Temperature Coefficient=-
FB4 FB5: library part dcp00209, "0402 (1005) 150OHM (TYP.) 1000MA", Current=1A, Manufacturer="Murata Electronics", Operating Temperature="-40°C ~ 85°C", Supplier Part Number 1=490-18375-1-ND, Temperature Coefficient=-
FC1: "Feed through capactior 27uF", Current=6A, Manufacturer=Murata, Operating Temperature="-40°C ~ 85°C", PartNumber=NFM31PC276B0J3L, Supplier Part Number 1=490-6984-1-ND, Temperature Coefficient=-, Tolerance=±20%, Voltage - Rated=6.3V
FID1 FID2 FID3: library part cmp00099, "Fiducial", Alt Manufacturer=-
H1 H3: "Hex Standoff Threaded M3 Nylon 1.260\" (32.00mm) Natural", Alt Manufacturer=-, Manufacturer="Essentra Components", Supplier Part Number 1=RPC3620-ND
J1: "FMC, High Density Array, Male / EVM Connector 40x10", Alt Manufacturer=-, Manufacturer=Samtec, Supplier Part Number 1=SAM8730-ND
J2: library part cmp00022, "Power Jack, mini, 2.1mm OD, R/A, TH", Alt Manufacturer=-, Manufacturer=Switchcraft, Supplier Part Number 1=SC1313-ND
J3: "USB - C (Type - C) USB 2.0 Receptacle Connector 24 Position Surface Mount, Right Angle; Through Hole", Manufacturer=GCT, Supplier Part Number 1=2073-USB4105-GF-ACT-ND
J4 J5 J6 J7 J8 J9 J10 J11: "SMA Connector Jack, Female Socket 50Ohm Surface Mount, Through Hole Solder", Alt Manufacturer=-, Manufacturer="Amphenol RF", Supplier Part Number 1=ACX1962-ND
J12: "Header, 100mil, 3x1, Gold, TH", Alt Manufacturer="Sullins Connector Solutions", Alt PartNumber=PBC03SAAN, Color=-, Manufacturer=Samtec, Supplier Part Number 1=S1011E-03-ND
J13: library part cmp00298, "Header, 50mil, 2x1, Gold, TH", Alt Manufacturer=-, Manufacturer="Sullins Connector Solutions", Supplier Part Number 1=S9014E-02-ND
L1 L2 L3 L4: library part LQG15HSR18J02D, "Inductor, Multilayer, Air Core, 180 nH, 0.14 A, 3.38 ohm, SMD", Manufacturer=MuRata, Supplier Part Number 1=490-2638-1-ND, Value1="3.38 ohm", Value2=0.14A, ValueDisplayed=180nH
LBL1: library part cmp00106, "Thermal Transfer Printable Labels, 0.650\" W x 0.200\" H - 10,000 per roll", Alt Manufacturer=-, Manufacturer=Brady, Supplier Part Number 1=2267-THT-14-423-10-ND
Logo1: library part cmp00105, "FDL", Alt Manufacturer=-
Logo2: library part cmp00102, "FCC_disclaimer", Alt Manufacturer=-
Logo3: library part cmp00317, Alt Manufacturer=-, PartNumber="ESD Logo"
Logo4: library part cmp00101, Alt Manufacturer=-, PartNumber=WEEE_Minimum
LOGO5: library part cmp00103, "CE_Mark", Alt Manufacturer=-
Logo6: library part cmp00104, "Texas Instrument Corporate Signature", Alt Manufacturer=-, PartNumber="TI Bug"
PP1 PP3 PP4 PP5 PP6 PP7 PP8 PP9 PP10: "Probe Point that can be used in lue of a test point", Alt Manufacturer=-
PP2: library part cmp00025, "Probe Point that can be used in lue of a test point", Alt Manufacturer=-
Q1: library part cmp00159, "MOSFET, N-CH, 20 V, 10 A", Alt Manufacturer=-, Manufacturer="Texas Instruments", Supplier Part Number 1=296-39992-1-ND
Q2 Q3: "MOSFET, N-CH, 12 V, 3.6 A, YJM0003A (PICOSTAR-3)", Manufacturer="Texas Instruments", Supplier Part Number 1=CSD13380F3-ND
R1: library part RSMD040200361, "RES SMD 100K OHM 0.5% 1/16W 0402", Manufacturer="Panasonic Electronic Components", Operating Temperature="-55°C ~ 155°C", Power (Watts)="0.063W, 1/16W", Ratings=AEC-Q200, Resistance="100 kΩ", Supplier Part Number 1=P100KDECT-ND, Temperature Coefficient=±25ppm/°C, Tolerance=±0.5%
R2: library part RSMD040202774, "RES SMD 45.3K OHM 1% 1/10W 0402", Manufacturer="Panasonic Electronic Components", Operating Temperature="-55°C ~ 155°C", Power (Watts)="0.1W, 1/10W", Ratings=AEC-Q200, Resistance="45.3 kΩ", Supplier Part Number 1=P45.3KLCT-ND, Temperature Coefficient=±100ppm/°C, Tolerance=±1%
R3 R18 R25: library part RSMD080502076, "RES 10K OHM 1% 1/2W 0805", Manufacturer="Panasonic Electronic Components", Operating Temperature="-55°C ~ 175°C", Power (Watts)="0.5W, 1/2W", Ratings=AEC-Q200, Resistance="10 kΩ", Supplier Part Number 1=10-ERJ-HP6F1002VCT-ND, Temperature Coefficient=±100ppm/°C, Tolerance=±1%
R4: library part RSMD040200899, "RES SMD 16.2KOHM 0.1% 1/16W 0402", Manufacturer="Panasonic Electronic Components", Operating Temperature="-55°C ~ 155°C", Power (Watts)="0.063W, 1/16W", Ratings=AEC-Q200, Resistance="16.2 kΩ", Supplier Part Number 1=P16.2KDCCT-ND, Temperature Coefficient=±25ppm/°C, Tolerance=±0.1%
R5 R6 R10 R15 R24 R32 R33 R34 R37 R47 R48 R49 R51 R52 R53 R54 R55 R56 R58 R59 R60 R61 R62 R73 R101 R110 R122 R147 R148: library part RSMD040200315, "RES SMD 10K OHM 0.1% 1/16W 0402", Manufacturer="Panasonic Electronic Components", Operating Temperature="-55°C ~ 155°C", Power (Watts)="0.063W, 1/16W", Ratings=AEC-Q200, Resistance="10 kΩ", Supplier Part Number 1=P10KDCCT-ND, Temperature Coefficient=±25ppm/°C, Tolerance=±0.1%
R7: library part RSMD040202418, "RES SMD 37.4KOHM 0.1% 1/16W 0402", Manufacturer="Panasonic Electronic Components", Operating Temperature="-55°C ~ 155°C", Power (Watts)="0.063W, 1/16W", Ratings=AEC-Q200, Resistance="37.4 kΩ", Supplier Part Number 1=P37.4KDCCT-ND, Temperature Coefficient=±25ppm/°C, Tolerance=±0.1%
R8 R21 R30 R46: library part RSMD040200519, "RES SMD 12K OHM 1% 1/10W 0402", Manufacturer="Panasonic Electronic Components", Operating Temperature="-55°C ~ 155°C", Power (Watts)="0.1W, 1/10W", Ratings=AEC-Q200, Resistance="12 kΩ", Supplier Part Number 1=P12.0KLCT-ND, Temperature Coefficient=±100ppm/°C, Tolerance=±1%
R9 R22 R23 R31 R121 R128: library part RSMD040200004, "RES 0 OHM JUMPER 0402 SMD", Manufacturer="Panasonic Electronic Components", Operating Temperature="-55°C ~ 155°C", Power (Watts)="0.1W, 1/10W", Ratings=AEC-Q200, Resistance="0 Ω", Supplier Part Number 1=10-ERJ-U020R00XCT-ND, Temperature Coefficient="-100/ +600ppm/°C", Tolerance=Jumper
R11 R16 R26: library part RSMD040200314, "RES SMD 10K OHM 1% 1/10W 0402", Manufacturer="Panasonic Electronic Components", Operating Temperature="-55°C ~ 155°C", Power (Watts)="0.1W, 1/10W", Ratings=AEC-Q200, Resistance="10 kΩ", Supplier Part Number 1=P10.0KLCT-ND, Temperature Coefficient=±100ppm/°C, Tolerance=±1%
R12: library part RSMD040203923, "RES SMD 9.31KOHM 0.1% 1/16W 0402", Manufacturer="Panasonic Electronic Components", Operating Temperature="-55°C ~ 155°C", Power (Watts)="0.063W, 1/16W", Ratings=AEC-Q200, Resistance="9.31 kΩ", Supplier Part Number 1=P9.31KDCCT-ND, Temperature Coefficient=±25ppm/°C, Tolerance=±0.1%
R13: library part RSMD040203748, "RES SMD 80.6K OHM 1% 1/10W 0402", Manufacturer="Panasonic Electronic Components", Operating Temperature="-55°C ~ 155°C", Power (Watts)="0.1W, 1/10W", Ratings=AEC-Q200, Resistance="80.6 kΩ", Supplier Part Number 1=P80.6KLCT-ND, Temperature Coefficient=±100ppm/°C, Tolerance=±1%
R14: library part RSMD040202615, "RES SMD 4.87KOHM 0.1% 1/16W 0402", Manufacturer="Panasonic Electronic Components", Operating Temperature="-55°C ~ 155°C", Power (Watts)="0.063W, 1/16W", Ratings=AEC-Q200, Resistance="4.87 kΩ", Supplier Part Number 1=P4.87KDCCT-ND, Temperature Coefficient=±25ppm/°C, Tolerance=±0.1%
R17 R27: "RES 0.1 OHM 1% 2/5W 0603", Manufacturer="Vishay Dale", Power (Watts)="0.4W, 2/5W", Resistance="3 mΩ", Supplier Part Number 1=541-10032-1-ND, Tolerance=±1%
R19 R28: library part RSMD040203878, "RES SMD 88.7KOHM 0.1% 1/16W 0402", Manufacturer=Yageo, Operating Temperature="-55°C ~ 155°C", Power (Watts)="0.063W, 1/16W", Ratings=AEC-Q200, Resistance="88.7 kΩ", Supplier Part Number 1=YAG1486CT-ND, Temperature Coefficient=±25ppm/°C, Tolerance=±0.1%
R20 R29: library part RSMD040200551, "RES SMD 12.4KOHM 0.1% 1/16W 0402", Manufacturer="Panasonic Electronic Components", Operating Temperature="-55°C ~ 155°C", Power (Watts)="0.063W, 1/16W", Ratings=AEC-Q200, Resistance="12.4 kΩ", Supplier Part Number 1=P12.4KDCCT-ND, Temperature Coefficient=±25ppm/°C, Tolerance=±0.1%
R35 R38: library part RSMD040202594, "RES SMD 4.7K OHM 1% 1/10W 0402", Manufacturer="Panasonic Electronic Components", Operating Temperature="-55°C ~ 155°C", Power (Watts)="0.1W, 1/10W", Ratings=AEC-Q200, Resistance="4.7 kΩ", Supplier Part Number 1=P4.70KLCT-ND, Temperature Coefficient=±100ppm/°C, Tolerance=±1%
R36 R39 R63 R64 R68 R69 R74 R75 R78 R81 R82 R83 R86 R87 R90 R93 R94 R95 R98 R99 R100 R102 R103 R104 R105 R106 R111 R112 R113 R114 R115 R116 R117 R118 R119 R123 R125 R126 R127 R129 R131 R137 R138 R139 R140 R141 R142 R143 R144 R146 R152 R153 R154 R155 R156 R157 R158 R159 R160 R161 R162 R163 R164 R165 R166 R167 R168 R169 R170 R171 R172 R173 R174 R175 R176 R177 R178 R179 R180 R181: library part RSMD020101699, "RES SMD 0 OHM JUMPER 1/20W 0201", Manufacturer="Panasonic Electronic Components", Operating Temperature="-55°C ~ 125°C", Power (Watts)="0.05W, 1/20W", Resistance="0 Ω", Supplier Part Number 1=P15979CT-ND, Tolerance=Jumper
R40 R57 R149 R150: library part RSMD040200375, "RES SMD 100 OHM 1% 1/10W 0402", Manufacturer="Panasonic Electronic Components", Operating Temperature="-55°C ~ 155°C", Power (Watts)="0.1W, 1/10W", Ratings=AEC-Q200, Resistance="100 Ω", Supplier Part Number 1=P100LCT-ND, Temperature Coefficient=±100ppm/°C, Tolerance=±1%
R41 R43 R44: library part RSMD040200327, "RES SMD 10 OHM 5% 1/10W 0402", Manufacturer="Panasonic Electronic Components", Operating Temperature="-55°C ~ 155°C", Power (Watts)="0.1W, 1/10W", Ratings=AEC-Q200, Resistance="10 Ω", Supplier Part Number 1=P10JCT-ND, Temperature Coefficient=±200ppm/°C, Tolerance=±5%
R42 R107 R108 R109: library part RSMD080510615, "RES SMD 0 OHM JUMPER 1/8W 0805", Manufacturer="Panasonic Electronic Components", Operating Temperature="-55°C ~ 155°C", Power (Watts)="0.125W, 1/8W", Ratings=AEC-Q200, Resistance="0 Ω", Supplier Part Number 1=P0.0ACT-ND, Temperature Coefficient=-, Tolerance=Jumper
R45 R50: library part RSMD040201206, "RES SMD 2.2K OHM 5% 1/10W 0402", Manufacturer="Panasonic Electronic Components", Operating Temperature="-55°C ~ 155°C", Power (Watts)="0.1W, 1/10W", Ratings=AEC-Q200, Resistance="2.2 kΩ", Supplier Part Number 1=P2.2KJCT-ND, Temperature Coefficient=±200ppm/°C, Tolerance=±5%
R65 R67 R71: library part RSMD020100177, "RES SMD 49.9 OHM 1% 1/20W 0201", Manufacturer="Panasonic Electronic Components", Operating Temperature="-55°C ~ 125°C", Power (Watts)="0.05W, 1/20W", Resistance="49.9 Ω", Supplier Part Number 1=P123049CT-ND, Temperature Coefficient=±200ppm/°C, Tolerance=±1%
R66 R70 R72: library part RSMD020100143, "RES SMD 1K OHM 1% 1/20W 0201", Manufacturer="Panasonic Electronic Components", Operating Temperature="-55°C ~ 125°C", Power (Watts)="0.05W, 1/20W", Resistance="1 kΩ", Supplier Part Number 1=P122413CT-ND, Temperature Coefficient=±200ppm/°C, Tolerance=±1%
R76 R84 R88 R96: library part RSMD020100013, "RES SMD 33 OHM 1% 1/20W 0201", Manufacturer="Panasonic Electronic Components", Operating Temperature="-55°C ~ 125°C", Power (Watts)="0.05W, 1/20W", Resistance="33 Ω", Supplier Part Number 1=P122944CT-ND, Temperature Coefficient=±200ppm/°C, Tolerance=±1%
R77 R85 R89 R97: library part RSMD020100179, "RES SMD 10 OHM 1% 1/20W 0201", Manufacturer="Panasonic Electronic Components", Operating Temperature="-55°C ~ 125°C", Power (Watts)="0.05W, 1/20W", Resistance="10 Ω", Supplier Part Number 1=P122669CT-ND, Temperature Coefficient=±200ppm/°C, Tolerance=±1%
R79 R80 R91 R92: library part RSMD020100010, "RES SMD 24.9 OHM 1% 1/20W 0201", Manufacturer="Panasonic Electronic Components", Operating Temperature="-55°C ~ 125°C", Power (Watts)="0.05W, 1/20W", Resistance="24.9 Ω", Supplier Part Number 1=P122870CT-ND, Temperature Coefficient=±200ppm/°C, Tolerance=±1%
R120 R124: library part RSMD040200354, "RES SMD 100K OHM 5% 1/10W 0402", Manufacturer="Panasonic Electronic Components", Operating Temperature="-55°C ~ 155°C", Power (Watts)="0.1W, 1/10W", Ratings=AEC-Q200, Resistance="100 kΩ", Supplier Part Number 1=P100KJCT-ND, Temperature Coefficient=±200ppm/°C, Tolerance=±5%
R130: library part RSMD020100692, "RES SMD 2.49K OHM 1% 1/20W 0201", Manufacturer="Panasonic Electronic Components", Operating Temperature="-55°C ~ 125°C", Power (Watts)="0.05W, 1/20W", Resistance="2.49 kΩ", Supplier Part Number 1=P122865CT-ND, Temperature Coefficient=±200ppm/°C, Tolerance=±1%
R132: library part RSMD020100769, "RES SMD 3K OHM 1% 1/20W 0201", Manufacturer="Panasonic Electronic Components", Operating Temperature="-55°C ~ 125°C", Power (Watts)="0.05W, 1/20W", Resistance="3 kΩ", Supplier Part Number 1=P122912CT-ND, Temperature Coefficient=±200ppm/°C, Tolerance=±1%
R133: library part RSMD020100641, "RES SMD 4.99K OHM 1% 1/20W 0201", Manufacturer="Panasonic Electronic Components", Operating Temperature="-55°C ~ 125°C", Power (Watts)="0.05W, 1/20W", Resistance="4.99 kΩ", Supplier Part Number 1=P123046CT-ND, Temperature Coefficient=±200ppm/°C, Tolerance=±1%
R134 R135 R136: library part RSMD020101186, "RES SMD 10K OHM 5% 1/20W 0201", Manufacturer="Panasonic Electronic Components", Operating Temperature="-55°C ~ 125°C", Power (Watts)="0.05W, 1/20W", Resistance="10 kΩ", Supplier Part Number 1=P123222CT-ND, Temperature Coefficient=±200ppm/°C, Tolerance=±5%
R145: library part RSMD020100147, "RES SMD 220 OHM 1% 1/20W 0201", Manufacturer="Panasonic Electronic Components", Operating Temperature="-55°C ~ 125°C", Power (Watts)="0.05W, 1/20W", Resistance="220 Ω", Supplier Part Number 1=P122831CT-ND, Temperature Coefficient=±200ppm/°C, Tolerance=±1%
R151 R182: library part RSMD020101206, "RES SMD 12K OHM 5% 1/20W 0201", Manufacturer="Panasonic Electronic Components", Operating Temperature="-55°C ~ 125°C", Power (Watts)="0.05W, 1/20W", Resistance="12 kΩ", Supplier Part Number 1=P123235CT-ND, Temperature Coefficient=±200ppm/°C, Tolerance=±5%
SH-J12: library part cmp00299, "2 (1 x 2) Position Shunt Connector Black Closed Top 0.050\" (1.27mm) Gold", Alt Manufacturer=-, Manufacturer="Adam Tech", PartNumber=HMSC-G, Supplier Part Number 1=2057-HMSC-G-ND
SH-J13: "2 (1 x 2) Position Shunt Connector Black Closed Top 0.050\" (1.27mm) Gold", Alt Manufacturer=-, Manufacturer="Adam Tech", Supplier Part Number 1=2057-HMSC-G-ND
SW1: library part cmp00460, "SWITCH SLIDE SPDT 3A 120V", Alt Manufacturer=-, Current Rating (Amps)=3A, Manufacturer=E-Switch, Supplier Part Number 1=EG2481-ND, Voltage Rating - DC=120V
SW2 SW3: "Switch Slide SPDT 12V, 500mA", Alt Manufacturer=-, Manufacturer="Wurth Elektronik", PartNumber=450301014042, Supplier Part Number 1=710-450301014042
SW4: library part cmp00234, "SWITCH TACTILE SPST-NO 0.05A 24V", Alt Manufacturer=-, Manufacturer="TE Connectivity", Supplier Part Number 1=A101402CT-ND
SW5: "SWITCH SLIDE DIP SPST 0.1A 6V", Manufacturer="Nidec Components Corporation", Supplier Part Number 1=563-1005-1-ND
T1: "RF Transformer, 75 ohm, 1: 1, 0.4-800MHz, SMT", Frequency_Fixed=0.4-800MHz, Manufacturer=Mini-Circuits, Mouser Part Number=139-ADT1-1WT, Operating Temperature Range="-20°C to +85°C"
T2 T3: "Transformer 50Ω/0.03 to 125 MHz", Manufacturer=Mini-Circuits
TP1: library part cmp00040, "Test Point, Multipurpose, Red, TH", Alt Manufacturer=-, Color=Red, Manufacturer=Keystone, Supplier Part Number 1=36-5010-ND
TP2: library part cmp00047, "Test Point, Multipurpose, Brown, TH", Alt Manufacturer=-, Color=Brown, Manufacturer=Keystone, Supplier Part Number 1=36-5125-ND
TP3: library part cmp00057, "Test Point, Miniature, Green, TH", Alt Manufacturer=-, Color=Green, Manufacturer=Keystone, Supplier Part Number 1=36-5116-ND
U1: "14-Bit, 125-MSPS, Low-Noise, Ultra-Low Power Dual Channel ADC, RSB0040B (WQFN-40)", Alternate Manufacturer="Texas Instruments", Alternate PartNumber=ADC3644IRSBR, PartNumber=ADC3644IRSBT
U2: library part cmp00157, "12V, 5A, 30mΩ eFuse with Adjustable +/-15% Accurate Current Limit, DRC0010J (VSON-10)", Alt Manufacturer=-, Manufacturer="Texas Instruments"
U3: "17V Input 2A Synchronous Step-Down Converter MicroSiP Module With Integrated Inductor, SIL0008D (uSIP-8)", Alternate Manufacturer="Texas Instruments", Alternate PartNumber=TPS82140SILT
U4: library part cmp00201, "3-V to 17-V, 3-A Low-Noise and Low-Ripple Buck Power Module with Integrated Ferrite Bead Filter Compensation", Alt Manufacturer=-, Manufacturer="Texas Instruments", Max Supply Voltage=17V, Min Supply Voltage=3V, Nominal Supply Current=5mA, Operating Temperature Range="-55°C to +125°C", Output Voltage=0.8-5.5V, Part Number=TPSM82913RDUR, Switching Frequency=1/2.2MHz
U5 U7: "26V, 350kHz current sense amplifier", Alt Manufacturer="Texas Instruments", Alt PartNumber=INA180B1IDBVT
U6 U8: library part cmp00446, "2-A, ultra-low noise ultra-high PSRR RF voltage regulator", Alt Manufacturer=-, Manufacturer="Texas Instruments", PartNumber=TPS7A9601DSCR
U9: "16-Bit, 4-Channel, 1-kSPS, Delta-Sigma ADC with I2C Interface, RTE0016D (WQFN-16)", Alternate Manufacturer="Texas Instruments", Alternate PartNumber=ADS1119IRTET, Operating Temperature Range="-40 to 125 C"
U10: "Dual Bus Buffer Gate with 3-State Outputs, DCU0008A (VSSOP-8)", F @ Nom Voltage(Max)(Mhz)=150, Generic Part Number=SN74LVC2G125, ICC @ Nom Voltage(Max)(mA)=0.01, Manufacturer="Texas Instruments", Operating Temperature Range="-40 to 125 C", Rating=Catalog, tpd @ Nom Voltage(Max)(ns)=9.1,4.8,4.3,3.7, Voltage(Nom)(V)=1.8,2.5,3.3,5
U11: library part cmp00204, "USB Interface IC USB HS to Quad UART/ SPI/JTAG/I2C LQFP-6", Alt Manufacturer=FTDI, Alt PartNumber=FT4232HL-TRAY, Color=-, Supplier Part Number 1=768-1026-1-ND
U12: library part cmp00156, "1K Microwire Compatible Serial EEPROM", Alt Manufacturer=-, Manufacturer="Microchip Technology", Supplier Part Number 1=93LC46B-I/ST-ND
U13: library part cmp00307, "5-V low-leakage-current, 2: 1, 2-channel precision analog switch", Alt Manufacturer=-, Manufacturer="Texas Instruments", PartNumber=TMUX1136DQA, Supplier Part Number 1=296-TMUX1136DQARCT-ND
U14: library part cmp00170, "Translation - Voltage Levels 4-bit dual-supply bus transceiver with 3-state outputs and independent direction control inputs", Alt Manufacturer="Texas Instruments", Alt PartNumber=SN74AXC4T774BQB, Color=-
U15: "Low-Voltage 4-Bit 1-of-2 FET Multiplexer/Demultiplexe", Color=-, Manufacturer="Texas Instruments", PartNumber=SN74CBTLV3257RSVR, Supplier Part Number 1=296-35586-1-ND
U16 U23: "Single Bus Buffer Gate With 3-State Outputs. Active low enable.", Alt Manufacturer=-, Manufacturer="Texas Instruments"
U17: library part cmp00385, "1.4-pF on-state capacitance, 5-V, 2:1 (SPDT), 2-channel analog switch with powered-off protection", Alt Manufacturer=-, Manufacturer="Texas Instruments", PartNumber=TMUX136RSER
U18: library part cmp00229, "Push-pull, supply voltage supervisor with manual reset", Alt Manufacturer="Texas Instruments", Alt PartNumber=TPS3125J18DBVT, Color=-
U19: library part cmp00268, "SN74AUP1G08 Low-Power Single 2-Input Positive-AND Gate", Color=-, Manufacturer="Texas Instruments", Supplier Part Number 1=296-19075-1-ND
U20: library part cmp00301, "Ultra Low-Power, High-Precision Voltage Reference", Alt Manufacturer=-, Manufacturer="Texas Instruments"
U21: library part cmp00154, "EEPROM 64K 8KX8 1.8V SER EE IND 1/4AWP RPO", Alt Manufacturer=-, Manufacturer=Microchip, Supplier Part Number 1=24LC64FT-I/MNYCT-ND
U22: "16-ch, 0.8-V to 2.7-V high speed buffers with bus-hold and 3-state outputs", Alt Manufacturer=-, Manufacturer="Texas Instruments"
Y1: library part cmp00323, "12 MHz ±20ppm Crystal 18pF 60 Ohms 2-SMD, No Lead", Alt Manufacturer=-, Manufacturer="Abracon LLC", Supplier Part Number 1=815-ABM3-12-D2Y-T
ZZ1: library part cmp00108, "Assembly Notes", Alt Manufacturer=-

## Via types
v1: diameter 18, hole 8, Top Layer to Bottom Layer, tented both sides, 1001 vias
v2: diameter 40, hole 20, Top Layer to Bottom Layer, tented both sides, 14 vias
v3: diameter 18, hole 8, Top Layer to Bottom Layer, tented bottom, 4 vias

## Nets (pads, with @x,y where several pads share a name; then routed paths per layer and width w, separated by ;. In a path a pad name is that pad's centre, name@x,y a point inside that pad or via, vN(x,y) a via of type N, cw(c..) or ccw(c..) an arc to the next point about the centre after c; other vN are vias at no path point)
1p8V_AVDD: C21.2 C73.2 C74.2 C75.2 FB2.2 PP3.1 U1.5 U1.15 U1.36 U9.8 | length 2488.2
  Top Layer w8: v1(2071.2,1256.67) U1.5@2091.2,1256.67 ; v1(2177.82,1134.31) U1.15@2177.82,1154.31 ; U1.36@2177.82,1343.29 v1(2177.82,1363.29)
  L5 SIG w5: v1(1244.37,1893.18) 1270.87,1866.68 1316.83,1866.68 1336.5,1886.34 1381.84,1886.34 1608.18,1660 1755,1660 1775.12,1680.12 1857.77,1680.12 1859.9,1682.25 1871.91,1682.25 1874.04,1680.12 2031.74,1680.12 2044.95,1693.33 2223.48,1693.33 2236.31,1680.5 2294.03,1680.5 2329.94,1644.58 2491.79,1644.58 2549.15,1587.22 2549.15,951.23 2487.32,889.4 v1(2298.05,889.4)
  Bottom Layer w5: v1(1244.37,1893.18) U9.8@1249.37,1893.18
  Bottom Layer w8: v1(2071.2,1256.67) C74.2@2082.49,1256.67 ; C75.2@2170,1368.98 2170,1368.19 2175.93,1362.26 2176.79,1362.26 v1(2177.82,1363.29) ; v1(2177.82,1134.31) C73.2@2177.82,1144.88
  other v1: 708.74,1688.25 728.74,1688.25 708.74,1708.25 728.74,1708.25 708.74,1728.25 728.74,1728.25
1p8V_BUFVCC: C89.2 C90.2 C91.2 C92.2 C93.2 FC1.3 R151.2 U22.7 U22.18 U22.31 U22.42 | length 245.6
  Top Layer w8: R151.2@2667.05,1510.29 v1(2671.05,1510.29) ; C90.2@2940.28,1357.06 v1(2940.28,1366.91)
  Top Layer w9.7: C89.2@2575,1357.06 v1(2575,1366.91) ; v1(2940.28,1150.37) 2940.28,1148.13 2941.86,1146.54 2941.86,1143.94 C91.2@2945.28,1140.53
  Bottom Layer w8: v1(2575,1366.91) U22.42@2610,1366.91 v1(2645,1366.91) ; v1(2870.28,1366.91) U22.7@2905.28,1366.91 v1(2940.28,1366.91) ; U22.18@2905.28,1150.37 v1(2940.28,1150.37)
  Bottom Layer w9.7: v1(2575,1150.37) U22.31@2610,1150.37
  other v1: 996.48,1051.05 1016.48,1051.05 996.48,1071.05 1016.48,1071.05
